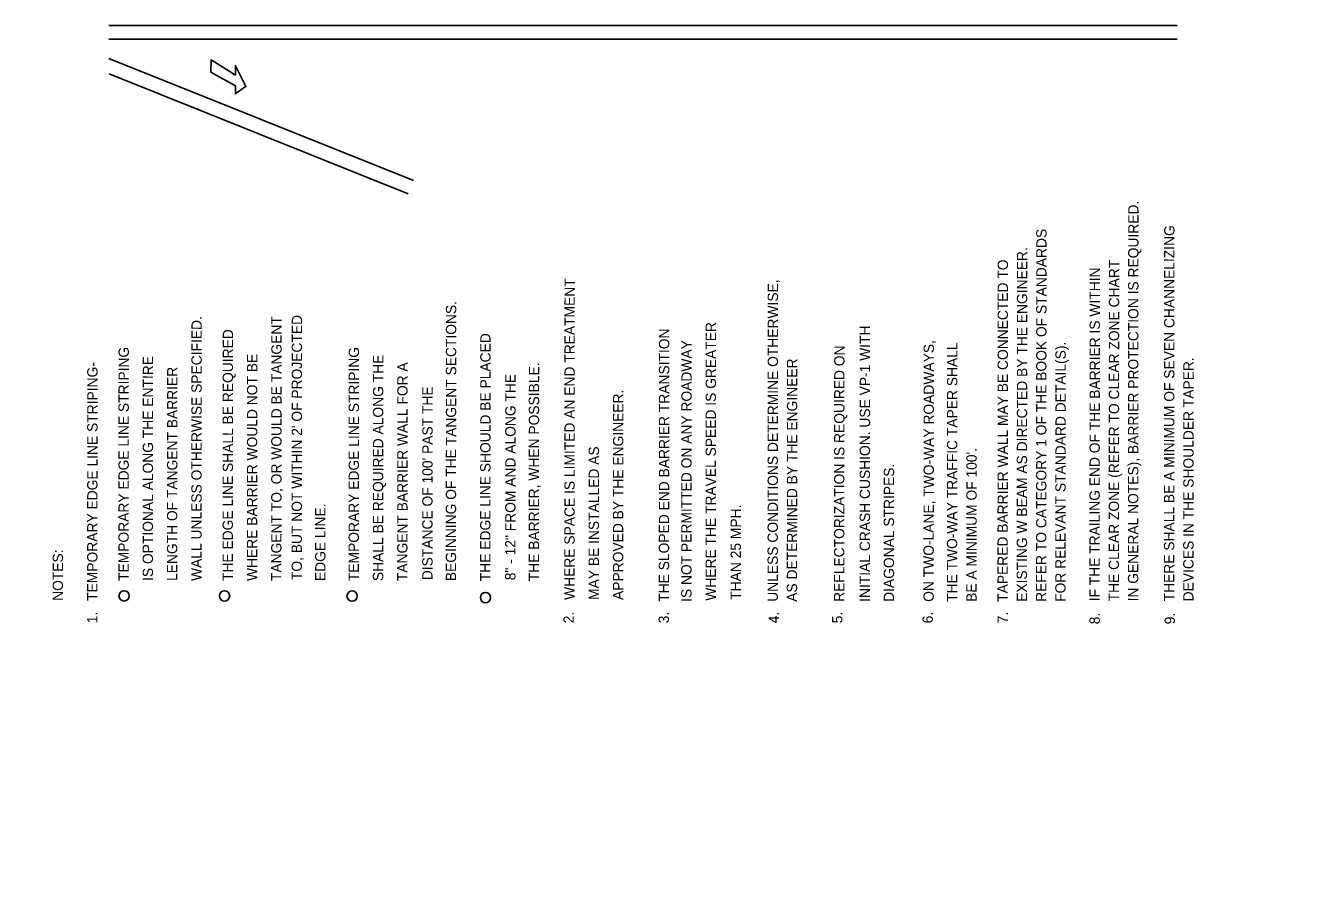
# Model space of a CAD drawing. Extents: x 612.5 to 619.9, y 611 to 621.1.
# Drawn here: x 612.48 to 619.85, y 611.03 to 616.04 of the extents above; entities that cross this region are included whole.
import ezdxf

# ---------------------------------------------------------------- set-up
doc = ezdxf.new("R2010")
doc.units = 0
for name, color, linetype in [('DETL-LINE', 7, 'Continuous'), ('DETL-NOTE', 7, 'Continuous'), ('TTLB-TEXT', 7, 'Continuous')]:
    doc.layers.add(name, color=color, linetype=linetype)

msp = doc.modelspace()

# ---------------------------------------------------------------- linework, layer by layer
at = {"layer": 'DETL-LINE'}
for p, q in [((612.9704, 616.0442), (619.1778, 616.0442)), ((612.9704, 615.9642), (619.1778, 615.9642)), ((614.7395, 615.1432), (612.9704, 615.8524)), ((613.5636, 615.8434), (613.5635, 615.7718)), ((613.7068, 615.7558), (613.5636, 615.8434)), ((614.7087, 615.0664), (612.9714, 615.7628)), ((613.5635, 615.7718), (613.7068, 615.6922)), ((613.7672, 615.6858), (613.7047, 615.8136)), ((613.7068, 615.8115), (613.7068, 615.7558)), ((613.7647, 615.6883), (613.7046, 615.6458)), ((613.7068, 615.6922), (613.7067, 615.6445))]:
    msp.add_line(p, q, dxfattribs=at)
at = {"layer": 'DETL-NOTE'}
for centre in [(613.0589, 612.7306), (613.6422, 612.7302), (614.3837, 612.7297), (615.1585, 612.7208)]:
    msp.add_circle(centre, 0.03, dxfattribs=at)
at = {"layer": 'TTLB-TEXT'}
for p, q in [((612.485, 612.1276), (612.485, 612.1276)), ((619.854, 611.0304), (619.854, 611.0304))]:
    msp.add_line(p, q, dxfattribs=at)

# ---------------------------------------------------------------- texts
at = {"layer": 'DETL-NOTE'}
for s, p in [('IN GENERAL NOTES), BARRIER PROTECTION IS REQUIRED.', (618.9512, 612.6986)), ('THERE SHALL BE A MINIMUM OF SEVEN CHANNELIZING ', (619.1603, 612.6989)), ('REFER TO CATEGORY 1 OF THE BOOK OF STANDARDS ', (618.417, 612.6959)), ('EXISTING W BEAM AS DIRECTED BY THE ENGINEER. ', (618.305, 612.696)), ('TAPERED BARRIER WALL MAY BE CONNECTED TO ', (618.193, 612.6961)), ('THE CLEAR ZONE (REFER TO CLEAR ZONE CHART', (618.8393, 612.6987)), ('IF THE TRAILING END OF THE BARRIER IS WITHIN ', (618.7273, 612.6988)), ('WHERE SPACE IS LIMITED AN END TREATMENT', (615.6763, 612.7072)), ('UNLESS CONDITIONS DETERMINE OTHERWISE, ', (616.8571, 612.6965)), ('BEGINNING OF THE TANGENT SECTIONS.', (614.9875, 612.8162)), ('WALL UNLESS OTHERWISE SPECIFIED.', (613.5088, 612.8172)), ('TANGENT TO, OR WOULD BE TANGENT ', (613.973, 612.8169)), ("TO, BUT NOT WITHIN 2' OF PROJECTED", (614.0917, 612.8224)), ('WHERE THE TRAVEL SPEED IS GREATER', (616.4968, 612.7026)), ('INITIAL CRASH CUSHION. USE VP-1 WITH ', (617.3923, 612.696)), ('THE EDGE LINE SHALL BE REQUIRED', (613.6907, 612.817)), ('THE EDGE LINE SHOULD BE PLACED', (615.1871, 612.816)), ('THE SLOPED END BARRIER TRANSITION', (616.2253, 612.6964)), ('IS NOT PERMITTED ON ANY ROADWAY', (616.3556, 612.6958)), ('TEMPORARY EDGE LINE STRIPING', (613.0853, 612.8175)), ('TEMPORARY EDGE LINE STRIPING', (614.4228, 612.8165)), ('REFLECTORIZATION IS REQUIRED ON', (617.2434, 612.696)), ('ON TWO-LANE, TWO-WAY ROADWAYS,', (617.7631, 612.696)), ('THE TWO-WAY TRAFFIC TAPER SHALL', (617.8992, 612.6959)), ('FOR RELEVANT STANDARD DETAIL(S).', (618.529, 612.6958)), ('TEMPORARY EDGE LINE STRIPING-', (612.9036, 612.7017)), ('IS OPTIONAL ALONG THE ENTIRE', (613.2265, 612.8174)), ('WHERE BARRIER WOULD NOT BE ', (613.8319, 612.817)), ('SHALL BE REQUIRED ALONG THE', (614.564, 612.8164)), ('TANGENT BARRIER WALL FOR A', (614.7051, 612.8164)), ('THE BARRIER, WHEN POSSIBLE.', (615.4695, 612.8158)), ('AS DETERMINED BY THE ENGINEER', (616.9691, 612.6964)), ('DEVICES IN THE SHOULDER TAPER.', (619.2723, 612.6988)), ('LENGTH OF TANGENT BARRIER', (613.3676, 612.8173)), ('8" - 12" FROM AND ALONG THE', (615.3326, 612.8215)), ("DISTANCE OF 100' PAST THE", (614.8507, 612.8218)), ('APPROVED BY THE ENGINEER.', (615.9587, 612.707)), ('MAY BE INSTALLED AS', (615.8176, 612.7072)), ("BE A MINIMUM OF 100'.", (618.0121, 612.696)), ('DIAGONAL STRIPES.', (617.5323, 612.6959)), ('EDGE LINE.', (614.2285, 612.8167)), ('THAN 25 MPH.', (616.6424, 612.7081)), ('NOTES:', (612.7036, 612.7018)), ('1.', (612.9036, 612.5714)), ('2.', (615.6714, 612.5714)), ('3.', (616.224, 612.5714)), ('4.', (616.863, 612.5714)), ('5.', (617.2321, 612.5714)), ('6.', (617.7579, 612.5714)), ('7.', (618.1941, 612.5714)), ('8.', (618.7276, 612.5656)), ('9.', (619.164, 612.5656))]:
    msp.add_text(s, height=0.06, rotation=89.96013, dxfattribs=at).set_placement(p)

doc.saveas('drawing.dxf')
